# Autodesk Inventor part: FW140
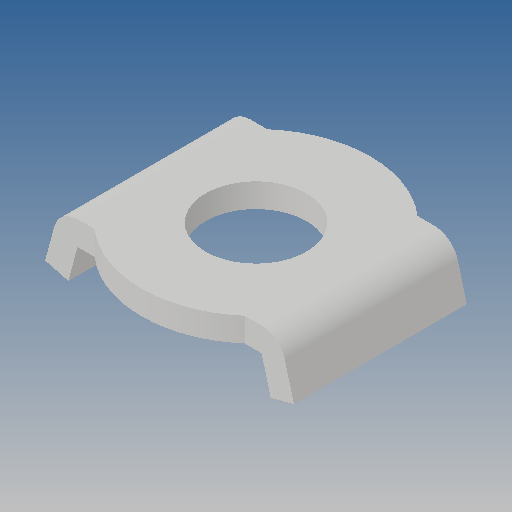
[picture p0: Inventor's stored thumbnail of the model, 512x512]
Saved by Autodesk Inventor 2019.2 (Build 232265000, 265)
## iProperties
Created: 2017-06
Part Number: FW140
Material: Ogólny
Document SubType Name: Modeling
Designer: CADENGINEERING4
Density: 1 g/cm^3
Appearance: Domyślna
Author: CADENGINEERING4
Revision Number: ÈÎºÎ
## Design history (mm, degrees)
feature "ÇÐ³ý-À­Éì1"
node "Bryła1"
